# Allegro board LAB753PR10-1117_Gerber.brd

Outline 342 x 150.28 mm; copper layers: TOP, GND1, IN1, IN2, VCC, IN3, IN4, GND2, IN5, IN6, GND3, BOTTOM. Coordinates in mm from the lower left corner of the outline.

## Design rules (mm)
net group BUF_CLK1: nets BUF_CLK1 BUF_CLK+
net group DIFFPAIR0: nets EDP_TX0#_C EDP_TX0_C
net group DIFFPAIR1: nets EDP_TX1#_C EDP_TX1_C
net group DIFFPAIR2: nets EDP_TX2#_C EDP_TX2_C
net group DIFFPAIR3: nets EDP_TX3#_C EDP_TX3_C
net group DIFFPAIR4: nets EDP_AUX#_C EDP_AUX_C
net group DIFFPAIR8: nets CLK_BUF_BCLK CLK_BUF_BCLK#
net group DIFFPAIR9: nets CLK_BUF_CKSSCD CLK_BUF_CKSSCD#
net group DIFFPAIR11: nets CPU_EDP_AUX CPU_EDP_AUX#
net group DIFFPAIR12: nets CLK_PCIE_LAN CLK_PCIE_LAN#
net group DIFFPAIR13: nets CLK_BUF_DMI CLK_BUF_DMI#
net group DIFFPAIR14: nets CLK_BUF_DOT96 CLK_BUF_DOT96#
net group DIFFPAIR15: nets CLK_CPU_DMI CLK_CPU_DMI#
net group DIFFPAIR16: nets CLK_CPU_DPLL CLK_CPU_DPLL#
net group DIFFPAIR17: nets CLK_CPU_SSC_DPLL CLK_CPU_SSC_DPLL#
net group DIFFPAIR18: nets CLK_PCIE_CD CLK_PCIE_CD#
net group DIFFPAIR19: nets CLK_PCIE_DGPU CLK_PCIE_DGPU#
net group DIFFPAIR22: nets CPU_DPB_CTRLCLK_R CPU_DPB_CTRLDAT_R
net group DIFFPAIR26: nets EC_SMB_CK1 EC_SMB_DA1
net group DIFFPAIR27: nets EC_SMB_CK2 EC_SMB_DA2
net group DIFFPAIR45: nets I2C_CLK I2C_DAT
net group DIFFPAIR47: nets M_CLK_DDR0 M_CLK_DDR#0
net group DIFFPAIR48: nets M_CLK_DDR1 M_CLK_DDR#1
net group DIFFPAIR49: nets M_CLK_DDR2 M_CLK_DDR#2
net group DIFFPAIR50: nets M_CLK_DDR3 M_CLK_DDR#3
net group DIFFPAIR55: nets PEX_TSTCLK_OUT PEX_TSTCLK_OUT#
net group DIFFPAIR61: nets VGA_SMB_CK2 VGA_SMB_DA2
net group DIFFPAIR65: nets CLK_PCIE_DGPU#_C CLK_PCIE_DGPU_C
net group DIFFPAIR66: nets VCCSENSE_VGA VSSSENSE_VGA
net group DIFFPAIR70: nets CSSN_1 CSSP_1
net group DIFFPAIR74: nets USB3RN5_L USB3RP5_L
net group DIFFPAIR77: nets PEG_GTX_HRX_C_N8 PEG_GTX_HRX_C_P8
net group DIFFPAIR78: nets PEG_GTX_HRX_C_N9 PEG_GTX_HRX_C_P9
net group DIFFPAIR79: nets PEG_GTX_HRX_C_N10 PEG_GTX_HRX_C_P10
net group DIFFPAIR80: nets PEG_GTX_HRX_C_N11 PEG_GTX_HRX_C_P11
net group DIFFPAIR85: nets TP_CLK TP_DATA
net group DIFFPAIR86: nets SATA_PTX_DRX_N5_C SATA_PTX_DRX_P5_C
net group DIFFPAIR87: nets SATA_PRX_DTX_N5_C SATA_PRX_DTX_P5_C
net group DIFFPAIR88: nets I2C_CLK_347 I2C_DAT_347
net group DIFFPAIR89: nets CDR_I2C_CLK CDR_I2C_DAT
net group DP1: nets DDR_A_DQS0 DDR_A_DQS#0
net group DP2: nets DDR_A_DQS1 DDR_A_DQS#1
net group DP3: nets DDR_A_DQS2 DDR_A_DQS#2
net group DP4: nets DDR_A_DQS3 DDR_A_DQS#3
net group DP5: nets DDR_A_DQS4 DDR_A_DQS#4
net group DP6: nets DDR_A_DQS5 DDR_A_DQS#5
net group DP7: nets DDR_A_DQS6 DDR_A_DQS#6
net group DP8: nets DDR_A_DQS7 DDR_A_DQS#7
net group DP9: nets DDR_B_DQS0 DDR_B_DQS#0
net group DP10: nets DDR_B_DQS1 DDR_B_DQS#1
net group DP11: nets DDR_B_DQS2 DDR_B_DQS#2
net group DP12: nets DDR_B_DQS3 DDR_B_DQS#3
net group DP13: nets DDR_B_DQS4 DDR_B_DQS#4
net group DP14: nets DDR_B_DQS5 DDR_B_DQS#5
net group DP15: nets DDR_B_DQS6 DDR_B_DQS#6
net group DP16: nets DDR_B_DQS7 DDR_B_DQS#7
net group DP17: nets FBA_CLK0 FBA_CLK0#
net group DP18: nets FBA_CLK1 FBA_CLK1#
net group DP19: nets FBA_WCK0 FBA_WCK0_N
net group DP20: nets FBA_WCK1 FBA_WCK1_N
net group DP21: nets FBA_WCK2 FBA_WCK2_N
net group DP22: nets FBA_WCK3 FBA_WCK3_N
net group FBC_CLK0: nets FBC_CLK0 FBC_CLK0#
net group FBC_CLK1: nets FBC_CLK1 FBC_CLK1#
net group FBC_WCK0: nets FBC_WCK0 FBC_WCK0_N
net group FBC_WCK1: nets FBC_WCK1 FBC_WCK1_N
net group FBC_WCK2: nets FBC_WCK2 FBC_WCK2_N
net group FBC_WCK3: nets FBC_WCK3 FBC_WCK3_N
net group PCIE_PRX_LANTX_3_C: nets PCIE_PRX_LANTX_N3_C PCIE_PRX_LANTX_P3_C
net group PECI: nets H_PECI PECI_KB9012
net group SATA_PRX_DTX_P1_C: nets SATA_PRX_DTX_N1_C SATA_PRX_DTX_P1_C
net group SATA_PRX_DTX_P3_C: nets SATA_PRX_DTX_N3_C SATA_PRX_DTX_P3_C
net group SATA_PRX_DTX_P4_C: nets SATA_PRX_DTX_N4_C SATA_PRX_DTX_P4_C
net group SATA_PTX_DRX_P1_C: nets SATA_PTX_DRX_N1_C SATA_PTX_DRX_P1_C
net group SATA_PTX_DRX_P3_C: nets SATA_PTX_DRX_N3_C SATA_PTX_DRX_P3_C
net group SATA_PTX_DRX_P4_C: nets SATA_PTX_DRX_N4_C SATA_PTX_DRX_P4_C
net group SML0: nets SML0CLK SML0DATA
net group 8: nets CFG0 CFG1 CFG2 CFG3 CFG4 CFG5 CFG6 CFG7 CFG8 CFG9 CFG10 CFG11 CFG12 CFG13 CFG14 CFG15 CFG16 CFG17 CFG18 CFG19
net group 10: nets AMP_LEFT AMP_LEFT_C AMP_RIGHT AMP_RIGHT_C HPOUT-L HPOUT-R MIC1 MIC1_C_L REMOTE1+ REMOTE1- REMOTE2+ REMOTE2- SPK_L1-_CONN SPK_L2+_CONN SPK_R1-_CONN SPK_R2+_CONN SPKL+ SPKL- SPKR+ SPKR-
net group 12: nets HDA_SPKR PCH_AZ_CODEC_SDIN0 PCH_AZ_CODEC_SDIN0_R PCH_AZ_CODEC_SDOUT PCH_AZ_CODEC_SYNC PCH_AZ_SDOUT PCH_AZ_SYNC PCH_AZ_SYNC_Q
net group 12/13.5: nets CPU_PLTRST# DDR3_DRAMRST# DGPU_PEX_RST# DGPU_PEX_RST#_R H_CPUPWRGD H_DRAMRST# H_PM_SYNC H_PROCHOT# H_PROCHOT#_R H_THERMTRIP# IMVP_PWRGD PCH_PLTRST# PCH_PWROK PCH_PWROK_R PCH_THRMTRIP#_R_R PLT_RST# PLT_RST#_R PM_APWROK_R PM_DRAM_PWRGD PM_DRAM_PWRGD_R PM_SYS_PWRGD_BUF SCLK SDA SYS_PWROK SYS_PWROK_R VCC_PGOOD VR_HOT# VR_HOT#1 XDP_TCLK
net group 15: nets PCH_AZ_BITCLK PCH_AZ_CODEC_BITCLK PCH_GPIO66 PEG_COMP SATA_COMP USBRBIAS
net group 20: nets +SA_DIMM_VREFDQ +SB_DIMM_VREFDQ +SM_VREF B+ CLK_PCH_14M CLK_PCI0 CLK_PCI1 CLK_PCI2 CLK_PCI_LPBACK CLK_PCI_LPC DMI_IREF DMI_RCOMP RJ45_MDI0+ RJ45_MDI0- RJ45_MDI1+ RJ45_MDI1- RJ45_MDI2+ RJ45_MDI2- RJ45_MDI3+ RJ45_MDI3- VCCSENSE VCCSENSE_R VSSSENSE VSSSENSE_R
net group 25: nets EDP_COMP SM_RCOMP0 SM_RCOMP1 SM_RCOMP2
net group 50: nets LAN_MDIN0 LAN_MDIN1 LAN_MDIN2 LAN_MDIN3 LAN_MDIP0 LAN_MDIP1 LAN_MDIP2 LAN_MDIP3
net group ASYNCHRONOUS: nets DGPU_HOLD_RST#
net group DDRA-CMD: nets DDR_A_BS0 DDR_A_BS1 DDR_A_BS2 DDR_A_CAS# DDR_A_MA0 DDR_A_MA1 DDR_A_MA2 DDR_A_MA3 DDR_A_MA4 DDR_A_MA5 DDR_A_MA6 DDR_A_MA7 DDR_A_MA8 DDR_A_MA9 DDR_A_MA10 DDR_A_MA11 DDR_A_MA12 DDR_A_MA13 DDR_A_MA14 DDR_A_MA15 DDR_A_RAS# DDR_A_WE#
net group DDRA-CTL: nets DDR_CKE0_DIMMA DDR_CKE1_DIMMA DDR_CS0_DIMMA# DDR_CS1_DIMMA# M_ODT0 M_ODT1
net group DDRA-D0: nets DDR_A_D0 DDR_A_D1 DDR_A_D2 DDR_A_D3 DDR_A_D4 DDR_A_D5 DDR_A_D6 DDR_A_D7
net group DDRA-D1: nets DDR_A_D8 DDR_A_D9 DDR_A_D10 DDR_A_D11 DDR_A_D12 DDR_A_D13 DDR_A_D14 DDR_A_D15
net group DDRA-D2: nets DDR_A_D16 DDR_A_D17 DDR_A_D18 DDR_A_D19 DDR_A_D20 DDR_A_D21 DDR_A_D22 DDR_A_D23
net group DDRA-D3: nets DDR_A_D24 DDR_A_D25 DDR_A_D26 DDR_A_D27 DDR_A_D28 DDR_A_D29 DDR_A_D30 DDR_A_D31
net group DDRA-D4: nets DDR_A_D32 DDR_A_D33 DDR_A_D34 DDR_A_D35 DDR_A_D36 DDR_A_D37 DDR_A_D38 DDR_A_D39
net group DDRA-D5: nets DDR_A_D40 DDR_A_D41 DDR_A_D42 DDR_A_D43 DDR_A_D44 DDR_A_D45 DDR_A_D46 DDR_A_D47
net group DDRA-D6: nets DDR_A_D48 DDR_A_D49 DDR_A_D50 DDR_A_D51 DDR_A_D52 DDR_A_D53 DDR_A_D54 DDR_A_D55
net group DDRA-D7: nets DDR_A_D56 DDR_A_D57 DDR_A_D58 DDR_A_D59 DDR_A_D60 DDR_A_D61 DDR_A_D62 DDR_A_D63
net group DDRB-CMD: nets DDR_B_BS0 DDR_B_BS1 DDR_B_BS2 DDR_B_CAS# DDR_B_MA0 DDR_B_MA1 DDR_B_MA2 DDR_B_MA3 DDR_B_MA4 DDR_B_MA5 DDR_B_MA6 DDR_B_MA7 DDR_B_MA8 DDR_B_MA9 DDR_B_MA10 DDR_B_MA11 DDR_B_MA12 DDR_B_MA13 DDR_B_MA14 DDR_B_MA15 DDR_B_RAS# DDR_B_WE#
net group DDRB-CTL: nets DDR_CKE2_DIMMB DDR_CKE3_DIMMB DDR_CS2_DIMMB# DDR_CS3_DIMMB# M_ODT2 M_ODT3
net group DDRB-D0: nets DDR_B_D0 DDR_B_D1 DDR_B_D2 DDR_B_D3 DDR_B_D4 DDR_B_D5 DDR_B_D6 DDR_B_D7
net group DDRB-D1: nets DDR_B_D8 DDR_B_D9 DDR_B_D10 DDR_B_D11 DDR_B_D12 DDR_B_D13 DDR_B_D14 DDR_B_D15
net group DDRB-D2: nets DDR_B_D16 DDR_B_D17 DDR_B_D18 DDR_B_D19 DDR_B_D20 DDR_B_D21 DDR_B_D22 DDR_B_D23
net group DDRB-D3: nets DDR_B_D24 DDR_B_D25 DDR_B_D26 DDR_B_D27 DDR_B_D28 DDR_B_D29 DDR_B_D30 DDR_B_D31
net group DDRB-D4: nets DDR_B_D32 DDR_B_D33 DDR_B_D34 DDR_B_D35 DDR_B_D36 DDR_B_D37 DDR_B_D38 DDR_B_D39
net group DDRB-D5: nets DDR_B_D40 DDR_B_D41 DDR_B_D42 DDR_B_D43 DDR_B_D44 DDR_B_D45 DDR_B_D46 DDR_B_D47
net group DDRB-D6: nets DDR_B_D48 DDR_B_D49 DDR_B_D50 DDR_B_D51 DDR_B_D52 DDR_B_D53 DDR_B_D54 DDR_B_D55
net group DDRB-D7: nets DDR_B_D56 DDR_B_D57 DDR_B_D58 DDR_B_D59 DDR_B_D60 DDR_B_D61 DDR_B_D62 DDR_B_D63
net group DIFFPAIR46: nets MIC_DATA
net group DMI: nets DMI_CRX_PTX_N0 DMI_CRX_PTX_N1 DMI_CRX_PTX_N2 DMI_CRX_PTX_N3 DMI_CRX_PTX_P0 DMI_CRX_PTX_P1 DMI_CRX_PTX_P2 DMI_CRX_PTX_P3 DMI_CTX_PRX_N0 DMI_CTX_PRX_N1 DMI_CTX_PRX_N2 DMI_CTX_PRX_N3 DMI_CTX_PRX_P0 DMI_CTX_PRX_P1 DMI_CTX_PRX_P2 DMI_CTX_PRX_P3
net group DP: nets CPU_MDP_N0 CPU_MDP_N1 CPU_MDP_N2 CPU_MDP_N3 CPU_MDP_P0 CPU_MDP_P1 CPU_MDP_P2 CPU_MDP_P3 MDP_LANE_N0_C MDP_LANE_N1_C MDP_LANE_N2_C MDP_LANE_N3_C MDP_LANE_P0_C MDP_LANE_P1_C MDP_LANE_P2_C MDP_LANE_P3_C PCH_DP_AUXN_C PCH_DP_AUXP_C PCH_DPC_AUX PCH_DPC_AUX#
net group EDP: nets CPU_EDP_TX0N CPU_EDP_TX0P CPU_EDP_TX1N CPU_EDP_TX1P CPU_EDP_TX2N CPU_EDP_TX2P CPU_EDP_TX3N CPU_EDP_TX3P
net group EMC: nets CLK_PCI3 CLK_PCI4 DISP_CLK_AUXP_CONN DISP_DAT_AUXN_CONN EC_ESB_CLK EC_ESB_DAT FC_D3 MIC_CLK PCH_AZ_CODEC_RST# PCH_AZ_RST# RJ45_CT0 RJ45_CT1 RJ45_CT2 RJ45_CT3 ROM_SCLK ROM_SCLK_R SPI_MOCLK SPI_MOCLK_R XTAL25_IN XTAL25_OUT XTAL_OUT XTALIN XTALOUT XTALSSIN XTLI XTLO
net group FBA-CMD: nets FBA_ABI#_H FBA_ABI#_L FBA_CAS#_H FBA_CAS#_L FBA_CKE_H FBA_CKE_L FBA_CS#_H FBA_CS#_L FBA_MA0_MA10_H FBA_MA0_MA10_L FBA_MA1_MA9_H FBA_MA1_MA9_L FBA_MA2_BA0_H FBA_MA2_BA0_L FBA_MA3_BA3_H FBA_MA3_BA3_L FBA_MA4_BA2_H FBA_MA4_BA2_L FBA_MA5_BA1_H FBA_MA5_BA1_L FBA_MA6_MA11_H FBA_MA6_MA11_L FBA_MA7_MA8_H FBA_MA7_MA8_L FBA_MA12_RFU_H FBA_MA12_RFU_L FBA_RAS#_H FBA_RAS#_L FBA_RST#_H FBA_RST#_L FBA_WE#_H FBA_WE#_L
net group FBA-D0: nets FBA_D0 FBA_D1 FBA_D2 FBA_D3 FBA_D4 FBA_D5 FBA_D6 FBA_D7
net group FBA-D1: nets FBA_D8 FBA_D9 FBA_D10 FBA_D11 FBA_D12 FBA_D13 FBA_D14 FBA_D15
net group FBA-D2: nets FBA_D16 FBA_D17 FBA_D18 FBA_D19 FBA_D20 FBA_D21 FBA_D22 FBA_D23
net group FBA-D3: nets FBA_D24 FBA_D25 FBA_D26 FBA_D27 FBA_D28 FBA_D29 FBA_D30 FBA_D31
net group FBA-D4: nets FBA_D32 FBA_D33 FBA_D34 FBA_D35 FBA_D36 FBA_D37 FBA_D38 FBA_D39
net group FBA-D5: nets FBA_D40 FBA_D41 FBA_D42 FBA_D43 FBA_D44 FBA_D45 FBA_D46 FBA_D47
net group FBA-D6: nets FBA_D48 FBA_D49 FBA_D50 FBA_D51 FBA_D52 FBA_D53 FBA_D54 FBA_D55
net group FBA-D7: nets FBA_D56 FBA_D57 FBA_D58 FBA_D59 FBA_D60 FBA_D61 FBA_D62 FBA_D63
net group FBA-DBI: nets FBA_DBI0# FBA_DBI1# FBA_DBI2# FBA_DBI3# FBA_DBI4# FBA_DBI5# FBA_DBI6# FBA_DBI7#
net group FBA-EDC: nets FBA_EDC0 FBA_EDC1 FBA_EDC2 FBA_EDC3 FBA_EDC4 FBA_EDC5 FBA_EDC6 FBA_EDC7
net group FBB-CLK: nets FBB_CLK0 FBB_CLK0# FBB_CLK1 FBB_CLK1#
net group FBB-CMD: nets FBB_ABI#_H FBB_ABI#_L FBB_CAS#_H FBB_CAS#_L FBB_CKE_H FBB_CKE_L FBB_CS#_H FBB_CS#_L FBB_MA0_MA10_H FBB_MA0_MA10_L FBB_MA1_MA9_H FBB_MA1_MA9_L FBB_MA2_BA0_H FBB_MA2_BA0_L FBB_MA3_BA3_H FBB_MA3_BA3_L FBB_MA4_BA2_H FBB_MA4_BA2_L FBB_MA5_BA1_H FBB_MA5_BA1_L FBB_MA6_MA11_H FBB_MA6_MA11_L FBB_MA7_MA8_H FBB_MA7_MA8_L FBB_MA12_RFU_H FBB_MA12_RFU_L FBB_RAS#_H FBB_RAS#_L FBB_RST#_H FBB_RST#_L FBB_WE#_H FBB_WE#_L
net group FBB-D0: nets FBB_D0 FBB_D1 FBB_D2 FBB_D3 FBB_D4 FBB_D5 FBB_D6 FBB_D7
net group FBB-D1: nets FBB_D8 FBB_D9 FBB_D10 FBB_D11 FBB_D12 FBB_D13 FBB_D14 FBB_D15
net group FBB-D2: nets FBB_D16 FBB_D17 FBB_D18 FBB_D19 FBB_D20 FBB_D21 FBB_D22 FBB_D23
net group FBB-D3: nets FBB_D24 FBB_D25 FBB_D26 FBB_D27 FBB_D28 FBB_D29 FBB_D30 FBB_D31
net group FBB-D4: nets FBB_D32 FBB_D33 FBB_D34 FBB_D35 FBB_D36 FBB_D37 FBB_D38 FBB_D39
net group FBB-D5: nets FBB_D40 FBB_D41 FBB_D42 FBB_D43 FBB_D44 FBB_D45 FBB_D46 FBB_D47
net group FBB-D6: nets FBB_D48 FBB_D49 FBB_D50 FBB_D51 FBB_D52 FBB_D53 FBB_D54 FBB_D55
net group FBB-D7: nets FBB_D56 FBB_D57 FBB_D58 FBB_D59 FBB_D60 FBB_D61 FBB_D62 FBB_D63
net group FBB-DBI: nets FBB_DBI0# FBB_DBI1# FBB_DBI2# FBB_DBI3# FBB_DBI4# FBB_DBI5# FBB_DBI6# FBB_DBI7#
net group FBB-EDC: nets FBB_EDC0 FBB_EDC1 FBB_EDC2 FBB_EDC3 FBB_EDC4 FBB_EDC5 FBB_EDC6 FBB_EDC7
net group FBB-WCK: nets FBB_WCK0 FBB_WCK0_N FBB_WCK1 FBB_WCK1_N FBB_WCK2 FBB_WCK2_N FBB_WCK3 FBB_WCK3_N
net group FBC-CMD: nets FBC_ABI#_H FBC_ABI#_L FBC_CAS#_H FBC_CAS#_L FBC_CKE_H FBC_CKE_L FBC_CS#_H FBC_CS#_L FBC_MA0_MA10_H FBC_MA0_MA10_L FBC_MA1_MA9_H FBC_MA1_MA9_L FBC_MA2_BA0_H FBC_MA2_BA0_L FBC_MA3_BA3_H FBC_MA3_BA3_L FBC_MA4_BA2_H FBC_MA4_BA2_L FBC_MA5_BA1_H FBC_MA5_BA1_L FBC_MA6_MA11_H FBC_MA6_MA11_L FBC_MA7_MA8_H FBC_MA7_MA8_L FBC_MA12_RFU_H FBC_MA12_RFU_L FBC_RAS#_H FBC_RAS#_L FBC_RST#_H FBC_RST#_L FBC_WE#_H FBC_WE#_L
net group FBC-D0: nets FBC_D0 FBC_D1 FBC_D2 FBC_D3 FBC_D4 FBC_D5 FBC_D6 FBC_D7
net group FBC-D1: nets FBC_D8 FBC_D9 FBC_D10 FBC_D11 FBC_D12 FBC_D13 FBC_D14 FBC_D15
net group FBC-D2: nets FBC_D16 FBC_D17 FBC_D18 FBC_D19 FBC_D20 FBC_D21 FBC_D22 FBC_D23
net group FBC-D3: nets FBC_D24 FBC_D25 FBC_D26 FBC_D27 FBC_D28 FBC_D29 FBC_D30 FBC_D31
net group FBC-D4: nets FBC_D32 FBC_D33 FBC_D34 FBC_D35 FBC_D36 FBC_D37 FBC_D38 FBC_D39
net group FBC-D5: nets FBC_D40 FBC_D41 FBC_D42 FBC_D43 FBC_D44 FBC_D45 FBC_D46 FBC_D47
net group FBC-D6: nets FBC_D48 FBC_D49 FBC_D50 FBC_D51 FBC_D52 FBC_D53 FBC_D54 FBC_D55
net group FBC-D7: nets FBC_D56 FBC_D57 FBC_D58 FBC_D59 FBC_D60 FBC_D61 FBC_D62 FBC_D63
net group FBC-DBI: nets FBC_DBI0# FBC_DBI1# FBC_DBI2# FBC_DBI3# FBC_DBI4# FBC_DBI5# FBC_DBI6# FBC_DBI7#
net group FBC-EDC: nets FBC_EDC0 FBC_EDC1 FBC_EDC2 FBC_EDC3 FBC_EDC4 FBC_EDC5 FBC_EDC6 FBC_EDC7
net group FBD-CLK: nets FBD_CLK0 FBD_CLK0# FBD_CLK1 FBD_CLK1#
net group FBD-CMD: nets FBD_ABI#_H FBD_ABI#_L FBD_CAS#_H FBD_CAS#_L FBD_CKE_H FBD_CKE_L FBD_CS#_H FBD_CS#_L FBD_MA0_MA10_H FBD_MA0_MA10_L FBD_MA1_MA9_H FBD_MA1_MA9_L FBD_MA2_BA0_H FBD_MA2_BA0_L FBD_MA3_BA3_H FBD_MA3_BA3_L FBD_MA4_BA2_H FBD_MA4_BA2_L FBD_MA5_BA1_H FBD_MA5_BA1_L FBD_MA6_MA11_H FBD_MA6_MA11_L FBD_MA7_MA8_H FBD_MA7_MA8_L FBD_MA12_RFU_H FBD_MA12_RFU_L FBD_RAS#_H FBD_RAS#_L FBD_RST#_H FBD_RST#_L FBD_WE#_H FBD_WE#_L
net group FBD-D0: nets FBD_D0 FBD_D1 FBD_D2 FBD_D3 FBD_D4 FBD_D5 FBD_D6 FBD_D7
net group FBD-D1: nets FBD_D8 FBD_D9 FBD_D10 FBD_D11 FBD_D12 FBD_D13 FBD_D14 FBD_D15
net group FBD-D2: nets FBD_D16 FBD_D17 FBD_D18 FBD_D19 FBD_D20 FBD_D21 FBD_D22 FBD_D23
net group FBD-D3: nets FBD_D24 FBD_D25 FBD_D26 FBD_D27 FBD_D28 FBD_D29 FBD_D30 FBD_D31 FBD_DBI3# FBD_EDC3
net group FBD-D4: nets FBD_D32 FBD_D33 FBD_D34 FBD_D35 FBD_D36 FBD_D37 FBD_D38 FBD_D39
net group FBD-D5: nets FBD_D40 FBD_D41 FBD_D42 FBD_D43 FBD_D44 FBD_D45 FBD_D46 FBD_D47
net group FBD-D6: nets FBD_D48 FBD_D49 FBD_D50 FBD_D51 FBD_D52 FBD_D53 FBD_D54 FBD_D55
net group FBD-D7: nets FBD_D56 FBD_D57 FBD_D58 FBD_D59 FBD_D60 FBD_D61 FBD_D62 FBD_D63
net group FBD-DBI: nets FBD_DBI0# FBD_DBI1# FBD_DBI2# FBD_DBI4# FBD_DBI5# FBD_DBI6# FBD_DBI7#
net group FBD-EDC: nets FBD_EDC0 FBD_EDC1 FBD_EDC2 FBD_EDC4 FBD_EDC5 FBD_EDC6 FBD_EDC7
net group FBD-WCK: nets FBD_WCK0 FBD_WCK0_N FBD_WCK1 FBD_WCK1_N FBD_WCK2 FBD_WCK2_N FBD_WCK3 FBD_WCK3_N
net group FDI: nets FDI_CSYNC FDI_INT FDI_IREF FDI_RCOMP
net group HDMI: nets CPU_HDMI_N0 CPU_HDMI_N1 CPU_HDMI_N2 CPU_HDMI_N3 CPU_HDMI_P0 CPU_HDMI_P1 CPU_HDMI_P2 CPU_HDMI_P3 TMDS_L_TX0N TMDS_L_TX0P TMDS_L_TX1N TMDS_L_TX1P TMDS_L_TX2N TMDS_L_TX2P TMDS_L_TXCN TMDS_L_TXCP TMDS_TX0N TMDS_TX0N_C TMDS_TX0P TMDS_TX0P_C TMDS_TX1N TMDS_TX1N_C TMDS_TX1P TMDS_TX1P_C TMDS_TX2N TMDS_TX2N_C TMDS_TX2P TMDS_TX2P_C TMDS_TXCN TMDS_TXCN_C TMDS_TXCP TMDS_TXCP_C
net group PCIE: nets PCIE_PRX_C_DTX_N1 PCIE_PRX_C_DTX_P1 PCIE_PRX_CARDTX_N5 PCIE_PRX_CARDTX_P5 PCIE_PRX_GLANTX_N3 PCIE_PRX_GLANTX_P3 PCIE_PRX_WLANTX_N4 PCIE_PRX_WLANTX_P4 PCIE_PTX_CARDRX_N5 PCIE_PTX_CARDRX_N5_C PCIE_PTX_CARDRX_P5 PCIE_PTX_CARDRX_P5_C PCIE_PTX_GLANRX_N3 PCIE_PTX_GLANRX_N3_C PCIE_PTX_GLANRX_P3 PCIE_PTX_GLANRX_P3_C PCIE_PTX_WLANRX_N4 PCIE_PTX_WLANRX_N4_C PCIE_PTX_WLANRX_P4 PCIE_PTX_WLANRX_P4_C
net group PEG: nets CRX_N8 CRX_N9 CRX_N10 CRX_N11 CRX_P8 CRX_P9 CRX_P10 CRX_P11 PEG_GTX_HRX_N0 PEG_GTX_HRX_N0_C PEG_GTX_HRX_N1 PEG_GTX_HRX_N1_C PEG_GTX_HRX_N2 PEG_GTX_HRX_N2_C PEG_GTX_HRX_N3 PEG_GTX_HRX_N3_C PEG_GTX_HRX_N4 PEG_GTX_HRX_N4_C PEG_GTX_HRX_N5 PEG_GTX_HRX_N5_C PEG_GTX_HRX_N6 PEG_GTX_HRX_N6_C PEG_GTX_HRX_N7 PEG_GTX_HRX_N7_C PEG_GTX_HRX_N8 PEG_GTX_HRX_N9 PEG_GTX_HRX_N10 PEG_GTX_HRX_N11 PEG_GTX_HRX_P0 PEG_GTX_HRX_P0_C PEG_GTX_HRX_P1 PEG_GTX_HRX_P1_C PEG_GTX_HRX_P2 PEG_GTX_HRX_P2_C PEG_GTX_HRX_P3 PEG_GTX_HRX_P3_C PEG_GTX_HRX_P4 PEG_GTX_HRX_P4_C PEG_GTX_HRX_P5 PEG_GTX_HRX_P5_C PEG_GTX_HRX_P6 PEG_GTX_HRX_P6_C PEG_GTX_HRX_P7 PEG_GTX_HRX_P7_C PEG_GTX_HRX_P8 PEG_GTX_HRX_P9 PEG_GTX_HRX_P10 PEG_GTX_HRX_P11 PEG_HTX_C_GRX_N0 PEG_HTX_C_GRX_N1 PEG_HTX_C_GRX_N2 PEG_HTX_C_GRX_N3 PEG_HTX_C_GRX_N4 PEG_HTX_C_GRX_N5 PEG_HTX_C_GRX_N6 PEG_HTX_C_GRX_N7 PEG_HTX_C_GRX_N8 PEG_HTX_C_GRX_N9 PEG_HTX_C_GRX_N10 PEG_HTX_C_GRX_N11 PEG_HTX_C_GRX_P0 PEG_HTX_C_GRX_P1 PEG_HTX_C_GRX_P2 PEG_HTX_C_GRX_P3 PEG_HTX_C_GRX_P4 PEG_HTX_C_GRX_P5 PEG_HTX_C_GRX_P6 PEG_HTX_C_GRX_P7 PEG_HTX_C_GRX_P8 PEG_HTX_C_GRX_P9 PEG_HTX_C_GRX_P10 PEG_HTX_C_GRX_P11 PEG_HTX_GRX_N0 PEG_HTX_GRX_N1 PEG_HTX_GRX_N2 PEG_HTX_GRX_N3 PEG_HTX_GRX_N4 PEG_HTX_GRX_N5 PEG_HTX_GRX_N6 PEG_HTX_GRX_N7 PEG_HTX_GRX_N8 PEG_HTX_GRX_N9 PEG_HTX_GRX_N10 PEG_HTX_GRX_N11 PEG_HTX_GRX_P0 PEG_HTX_GRX_P1 PEG_HTX_GRX_P2 PEG_HTX_GRX_P3 PEG_HTX_GRX_P4 PEG_HTX_GRX_P5 PEG_HTX_GRX_P6 PEG_HTX_GRX_P7 PEG_HTX_GRX_P8 PEG_HTX_GRX_P9 PEG_HTX_GRX_P10 PEG_HTX_GRX_P11
net group PLATFORM-CLK: nets CLK_PCIE_WLAN CLK_PCIE_WLAN# CLK_PCIE_WLAN#_R CLK_PCIE_WLAN_R CLK_PEG_GPU CLK_PEG_GPU# PCH_DPB_HDMI_CLK PCH_DPB_HDMI_DAT PCH_DPC_CLK PCH_DPC_DAT
net group RTC: nets PCH_RTCRST# PCH_RTCX1 PCH_RTCX1_R PCH_RTCX2 SRTCRST#
net group SATA: nets SATA_PRX_DTX_N0 SATA_PRX_DTX_N0_C SATA_PRX_DTX_N0_R SATA_PRX_DTX_N0_RC SATA_PRX_DTX_N1 SATA_PRX_DTX_N3 SATA_PRX_DTX_N4 SATA_PRX_DTX_N5 SATA_PRX_DTX_P0 SATA_PRX_DTX_P0_C SATA_PRX_DTX_P0_R SATA_PRX_DTX_P0_RC SATA_PRX_DTX_P1 SATA_PRX_DTX_P3 SATA_PRX_DTX_P4 SATA_PRX_DTX_P5 SATA_PTX_DRX_N0 SATA_PTX_DRX_N0_C SATA_PTX_DRX_N0_R SATA_PTX_DRX_N0_RC SATA_PTX_DRX_N1 SATA_PTX_DRX_N3 SATA_PTX_DRX_N4 SATA_PTX_DRX_N5 SATA_PTX_DRX_P0 SATA_PTX_DRX_P0_C SATA_PTX_DRX_P0_R SATA_PTX_DRX_P0_RC SATA_PTX_DRX_P1 SATA_PTX_DRX_P3 SATA_PTX_DRX_P4 SATA_PTX_DRX_P5
net group SD: nets SD_CD# SD_CLK MS_D0 SD_CLK MS_D0_R SD_CMD MS_D2 SD_CMD MS_D2_R SD_D0 MS_D1 SD_D0 MS_D1_R SD_D1 SD_D1_R SD_D2 MS_CLK SD_D2 MS_CLK_R SD_D3 MS_D3 SD_D3 MS_D3_R SD_WP MS_BS
net group SMBUS: nets BUF_SM_CLK BUF_SM_DAT MEM_SMBCLK MEM_SMBDATA PCH_SMBCLK PCH_SMBDATA SML1CLK SML1DATA
net group SPI: nets PCH_SPI_CLK PCH_SPI_CLK_R PCH_SPI_CS0# PCH_SPI_DO2 PCH_SPI_DO3 PCH_SPI_S0_R PCH_SPI_SI PCH_SPI_SI_R PCH_SPI_SO SPI_PCH_DO2_R SPI_PCH_DO3_R
net group SVID: nets ALERT# H_CPU_SVIDALRT# VIDALERT_N VIDSCLK VIDSOUT
net group USB20: nets USB20_CAM_N6_R USB20_CAM_P6_R USB20_N0 USB20_N0_CONN USB20_N1 USB20_N1_CONN USB20_N2 USB20_N2_CONN USB20_N3 USB20_N4 USB20_N5 USB20_N6 USB20_N7 USB20_N7_CONN USB20_N8 USB20_N8_CONN USB20_P0 USB20_P0_CONN USB20_P1 USB20_P1_CONN USB20_P2 USB20_P2_CONN USB20_P3 USB20_P4 USB20_P5 USB20_P6 USB20_P7 USB20_P7_CONN USB20_P8 USB20_P8_CONN
net group USB30: nets USB3RN1 USB3RN1_R USB3RN2 USB3RN2_R USB3RN3 USB3RN3_R USB3RN5 USB3RN5_R USB3RN6 USB3RN6_R USB3RP1 USB3RP1_R USB3RP2 USB3RP2_R USB3RP3 USB3RP3_R USB3RP5 USB3RP5_R USB3RP6 USB3RP6_R USB3TN1 USB3TN1_L USB3TN1_R USB3TN2 USB3TN2_L USB3TN2_R USB3TN3 USB3TN3_L USB3TN3_R USB3TN5 USB3TN5_R USB3TN6 USB3TN6_L USB3TN6_R USB3TP1 USB3TP1_L USB3TP1_R USB3TP2 USB3TP2_L USB3TP2_R USB3TP3 USB3TP3_L USB3TP3_R USB3TP5 USB3TP5_R USB3TP6 USB3TP6_L USB3TP6_R
net group XDP: nets XDP_BPM#0_R XDP_BPM#1_R XDP_BPM#2 XDP_BPM#3 XDP_BPM#4 XDP_BPM#5 XDP_BPM#6 XDP_BPM#7 XDP_DBRESET# XDP_DBRESET#_R XDP_PRDY# XDP_PREQ# XDP_TDI_R XDP_TDO_R XDP_TMS XDP_TRST#
nets with their own width: min track width 0.254; nets 3V3_MAIN_EN +1.35VS_VGAP AC/DC AM0 AM1 AM2 DIR_SEL ECAGND FBVDD_EN GPU_PGOOD HP2_D_L1 HP2_D_L2 HP2_D_R1 HP2_D_R2 JACK1_PLUG JACK1_PLUG# JACK1_PLUG_C JACK2_PLUG# MEM_VREF MIC_BIAS_B MIC_BIAS_C MIC_C_PLUG MIC_LINE_IN_L MIC_LINE_IN_R MPIO_2 MPIO_4_PB#_PD SENSE A# SPK_MUTE SPK_MUTE# SPK_MUTE#_R VCIN0_PH VDDQ_PLL
nets with their own width: min track width 0.508; nets 2.5VOUT +1.05V_+1.5V_RUN +1.5VS +1.35V +1.35V_PWRGD +1.35VS_VGA +1.35VS_VGAP_B+ +3.3V_AVDD +3.3V_DVDD +3.3V_F347_1 +3.3V_GFX_AON +3V_PCH +3VALW +3VLP +3VS +3VS_CAM +3VS_TOUCH +3VS_VGA +5VALW +5VALW_LED +5VS +AV12_DV12_S +AVDDL +DV33_18 +FB_PLLAVDD +FBA_VREFC +FBA_VREFD +FBB_VREFD +PCH_VCCDSW +PCH_VCCDSW3_3 +PCH_VCCDSW_R +V_TP +VCCIO_OUT +VREF_DQ_DIMMA +VREF_DQ_DIMMB AGND AMP_RIGHT-1 CPU_EDP_HPD DVDD_HDAIO GND I2C_CTL_EN N19248975 N21560268 N30064642 SNUB_+1.05V_GPUP
nets with their own width: min track width 1.016; nets +1.2VS +1.05VS_VGA +3.3V_F347 +3VS_DP +5VS_TP_LED +LAN_IO +PAVDD +PCH_VCCCFUSE +PVDD +VCC_3IN1 +VDD_TOUCH GPU_PLLVDD N27543768
nets with their own width: min track width 1.524; nets +0.675VS +3VS_CARD +HDMI_5V_OUT +INV_PWR_SRC +LCDVDD_CONN B+_BIAS
nets with their own width: min track width 2.032; nets +3VS_WLAN_NGFF +USB3_VCCA +USB3_VCCB
nets with their own width: min track width 2.286; nets +1.35VS_VGAP_B++
nets with their own width: min track width 4.064; nets +1.05VS

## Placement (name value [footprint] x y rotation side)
C1  0.1U_0402_16V7K  [C_0402]  117 49.47 90 top
C2  0.1U_0402_16V7K  [C_0402]  117.87 49.47 90 top
C3  22U_0805_6.3V6M  [C_0805]  105.95 63.27 180 top
C4  22U_0805_6.3V6M  [C_0805]  119.51 52.12 270 top
C5  22U_0805_6.3V6M  [C_0805]  108.93 52.86 180 top
C6  22U_0805_6.3V6M  [C_0805]  108.93 56.42 180 top
C7  22U_0805_6.3V6M  [C_0805]  108.93 54.64 180 top
C8  22U_0805_6.3V6M  [C_0805]  121.29 52.12 270 top
C9  0.022U_0402_16V7K  [C_0402]  80.75 42.78 270 bottom
C10  1U_0402_6.3V6K  [C_0402]  143.12 17.17 0 top
C11  0.1U_0402_16V7K  [C_0402]  143.12 18.06 0 top
C12  0.1U_0402_16V7K  [C_0402]  141.86 24.59 90 top
C13  0.1U_0402_16V7K  [C_0402]  142.75 24.59 90 top
C14  0.1U_0402_16V7K  [C_0402]  100.85 15.65 180 top
C15  2.2U_0603_10V6K  [C_0603]  101.09 14.57 180 top
C16  0.1U_0402_16V7K  [C_0402]  140.5 26.88 0 top
C17  0.1U_0402_16V4Z  [C_0402]  166.83 146.42 90 top
C27  0.1U_0402_16V4Z  [C_0402]  180.84 16.12 180 top
C29  0.1U_0402_16V4Z  [C_0402]  214.82 125.17 90 bottom
C256  10U_0603_6.3V6M  [C_0603]  61.6 14.76 270 top
C257  10U_0603_6.3V6M  [C_0603]  60.39 14.76 270 top
C258  0.1U_0402_16V7K  [C_0402]  52.61 14.81 0 bottom
C260  10U_0603_6.3V6M  [C_0603]  60.39 12.16 0 top
C261  10U_0603_6.3V6M  [C_0603]  60.52 10.44 270 top
C262  10U_0603_6.3V6M  [C_0603]  53.53 9.74 0 top
C263  10U_0603_6.3V6M  [C_0603]  53.53 11.01 0 top
C264  10U_0603_6.3V6M  [C_0603]  53.6 17.3 0 top
C265  10U_0603_6.3V6M  [C_0603]  53.6 16.03 0 top
C266  10U_0603_6.3V6M  [C_0603]  222.2 16.84 270 top
C267  10U_0603_6.3V6M  [C_0603]  223.41 16.84 270 top
C268  0.01U_0603_25V7K  [C_0603]  215.78 13.29 180 top
C269  10U_0603_6.3V6M  [C_0603]  215.78 14.56 180 top
C270  10U_0603_6.3V6M  [C_0603]  215.78 15.83 180 top
C2498  0.1U_0402_10V6K  [C_0402]  148.66 15.78 90 bottom
C2500  2200P_0402_25V7K  [C_0402]  129.67 117.07 270 top
C2502  2200P_0402_25V7K  [C_0402]  149.77 15.29 270 bottom
C2504  2200P_0402_25V7K  [C_0402]  149.76 13.55 270 bottom
C2505  2200P_0402_25V7K  [C_0402]  200.54 49.87 135 bottom
C2506  220P_0402_50V8J  [C_0402]  57.67 13.87 0 top
C2507  470P_0402_50V7K  [C_0402]  57.67 12.98 0 top
C2508  1U_0603_10V4Z~D  [C_0603]  210 125.52 90 bottom
C2509  0.1U_0402_25V6K~D  [C_0402]  212.17 121.71 180 bottom
CA1  0.1U_0402_25V6K~D  [C_0402]  22.29 17.13 0 bottom
CA3  0.1U_0402_25V6K~D  [C_0402]  15.98 17.4 180 bottom
CA4  0.1U_0402_25V6K~D  [C_0402]  18.01 21 0 top
CA5  10U_0603_6.3V6M~D  [C_0603]  18 22.15 90 top
CA6  10U_0603_6.3V6M~D  [C_0603]  16.63 9.54 225 top
CA7  0.1U_0402_25V6K~D  [C_0402]  20.28 8.74 90 top
CA8  0.1U_0402_25V6K~D  [C_0402]  18.85 7.41 90 bottom
CA9  0.1U_0402_25V6K~D  [C_0402]  22.27 15.05 0 bottom
CA10  0.1U_0402_25V6K~D  [C_0402]  20.4 18.93 180 bottom
CA11  0.1U_0402_25V6K~D  [C_0402]  16 19.73 270 bottom
CA13  2.2U_0603_10V6K  [C_0603]  25.19 12.92 0 bottom
CA14  0.1U_0402_25V6K~D  [C_0402]  22.4 20.86 180 top
CA15  2200P_0402_25V7K~D  [C_0402]  21.67 12.92 270 bottom
CA16  0.1U_0402_25V6K~D  [C_0402]  25.19 10.21 90 bottom
CA17  47U_0805_6.3V6M~D  [C_0805]  20.25 8.52 270 bottom
CA18  0.1U_0402_25V6K~D  [C_0402]  21.6 8.74 90 top
CA19  0.1U_0402_25V6K~D  [C_0402]  26.71 11.57 270 top
CA24  100P_0402_50V8J~D  [C_0402]  22.93 8.71 90 top
CA29  1000P_0402_50V7K  [C_0402]  34.15 16.25 270 top
CA30  10P_0402_50V8J~D  [C_0402]  24.01 21.86 90 top
CA31  1000P_0402_50V7K  [C_0402]  34.18 12.61 270 top
CA32  1000P_0402_50V7K  [C_0402]  34.19 9.95 90 top
CA33  1000P_0402_50V7K  [C_0402]  34.17 13.59 90 top
CA65  0.1U_0402_16V7K  [C_0402]  25.26 19.64 0 top
CA66  0.01U_0402_16V7K  [C_0402]  14.1 10.73 90 top
CA67  1U_0402_6.3V6K~D  [C_0402]  226.63 16.11 270 bottom
CA68  1U_0402_6.3V6K~D  [C_0402]  223.06 15.14 0 bottom
CA69  0.1U_0603  [C_0603]  28.84 10.31 0 top
CA70  0.1U_0603  [C_0603]  10.28 27.65 0 bottom
CA71  0.1U_0603  [C_0603]  22.96 14 180 bottom
CA72  0.01U_0402_16V7K  [C_0402]  13.21 10.73 90 top
CA73  0.1U_0402_16V7K  [C_0402]  21.67 10.25 90 bottom
CA74  0.1U_0402_16V7K  [C_0402]  16.03 11.86 90 bottom
CA75  0.1U_0402_16V7K  [C_0402]  29.39 10.4 180 bottom
CA76  2.2U_0603_10V6K  [C_0603]  22.9 12.6 270 bottom
CA77  2.2U_0603_10V6K  [C_0603]  24.12 12.05 270 bottom
CA81  10U_0603_6.3V6M~D  [C_0603]  5.12 6.4 0 bottom
CA83  330P_0402_50V  [C_0402]  4.66 19.17 270 bottom
CA84  330P_0402_50V  [C_0402]  3.71 19.17 270 bottom
CA85  330P_0402_50V  [C_0402]  1.72 20.91 270 bottom
CA86  330P_0402_50V  [C_0402]  2.59 20.89 270 bottom
CA89  220U_B2_2.5VM_R35M~D  [C_B2]  8.63 9.44 90 bottom
CA90  220U_B2_2.5VM_R35M~D  [C_B2]  11.88 10.94 90 bottom
CA94  1U_0603_25V6K  [C_0603]  3.05 31.71 180 bottom
CA95  1U_0603_25V6K  [C_0603]  3.05 30.51 180 bottom
CA96  1U_0603_25V6K  [C_0603]  7.47 19.1 0 bottom
CA97  1U_0603_25V6K  [C_0603]  7.47 20.33 0 bottom
CA98  10U_0805_25V6K  [C_0805]  9.81 21.85 90 bottom
CA99  1U_0603_25V6K  [C_0603]  6.96 31.26 45 bottom
CA100  1U_0603_25V6K  [C_0603]  7.83 30.39 45 bottom
CA101  0.1U_0402_16V4Z  [C_0402]  9.25 29.97 225 bottom
CA102  0.1U_0402_16V4Z  [C_0402]  5.09 32.9 270 bottom
CA103  0.1U_0402_16V4Z  [C_0402]  13.58 9.11 0 top
CA104  0.1U_0402_16V4Z  [C_0402]  8.47 7.41 0 top
CA105  2.2U_0603_10V6K  [C_0603]  11.62 8.85 270 top
CA106  2.2U_0603_10V6K  [C_0603]  10.42 8.85 270 top
CA107  0.22U_0603_25V7K  [C_0603]  6.29 19.65 135 bottom
CA108  0.22U_0603_25V7K  [C_0603]  3.64 22.3 315 bottom
CA109  0.22U_0603_25V7K  [C_0603]  1.78 29.43 270 bottom
CA110  0.22U_0603_25V7K  [C_0603]  2.97 23.03 135 bottom
CA112  1U_0402_10V6K  [C_0402]  27.26 16.35 180 bottom
CA113  2.2U_0603_10V6K  [C_0603]  10.95 17.01 90 bottom
CC1  0.22U_0402_16V7K  [C_0402]  154.93 82.43 0 bottom
CC2  0.22U_0402_16V7K  [C_0402]  152.59 83.87 0 bottom
CC3  0.22U_0402_16V7K  [C_0402]  154.93 85.2 0 bottom
CC4  0.22U_0402_16V7K  [C_0402]  152.9 86.8 0 bottom
CC5  0.22U_0402_16V7K  [C_0402]  154.93 88.01 0 bottom
CC6  0.22U_0402_16V7K  [C_0402]  153.09 89.47 0 bottom
CC7  0.22U_0402_16V7K  [C_0402]  154.93 90.79 0 bottom
CC8  0.22U_0402_16V7K  [C_0402]  152.59 92.06 0 bottom
CC9  0.22U_0402_16V7K  [C_0402]  168.53 138.04 90 bottom
CC10  0.22U_0402_16V7K  [C_0402]  170.44 139.03 90 bottom
CC11  0.22U_0402_16V7K  [C_0402]  172.37 137.92 90 bottom
CC12  0.22U_0402_16V7K  [C_0402]  174.39 139.22 90 bottom
CC13  0.22U_0402_16V7K  [C_0402]  154.93 81.5 0 bottom
CC14  0.22U_0402_16V7K  [C_0402]  152.59 82.94 0 bottom
CC15  0.22U_0402_16V7K  [C_0402]  154.93 84.27 0 bottom
CC16  0.22U_0402_16V7K  [C_0402]  152.9 85.87 0 bottom
CC17  0.22U_0402_16V7K  [C_0402]  154.93 87.08 0 bottom
CC18  0.22U_0402_16V7K  [C_0402]  153.09 88.49 0 bottom
CC19  0.22U_0402_16V7K  [C_0402]  154.93 89.86 0 bottom
CC20  0.22U_0402_16V7K  [C_0402]  152.59 91.13 0 bottom
CC21  0.22U_0402_16V7K  [C_0402]  167.62 138.04 90 bottom
CC22  0.22U_0402_16V7K  [C_0402]  169.55 139.03 90 bottom
CC23  0.22U_0402_16V7K  [C_0402]  171.48 137.92 90 bottom
CC24  0.22U_0402_16V7K  [C_0402]  173.47 139.22 90 bottom
CC27  100P_0402_50V8J  [C_0402]  93.54 64.87 270 top
CC28  0.1U_0402_16V7K  [C_0402]  91.76 63.1 270 top
CC29  100P_0402_50V8J  [C_0402]  91.24 96.8 0 top
CC30  0.1U_0402_16V7K  [C_0402]  88.64 64.8 0 top
CC31  0.01U_0402_16V7K  [C_0402]  82.67 63.02 0 top
CC32  2.2U_0603_10V6K  [C_0603]  88.97 103.92 180 bottom
CC33  10U_0603_6.3V6M  [C_0603]  107.25 79.78 180 top
CC34  10U_0603_6.3V6M  [C_0603]  109.67 79.78 180 top
CC35  10U_0603_6.3V6M  [C_0603]  119.64 79.78 0 top
CC36  10U_0603_6.3V6M  [C_0603]  117.22 79.78 0 top
CC37  10U_0603_6.3V6M  [C_0603]  115.95 79.78 180 top
CC38  10U_0603_6.3V6M  [C_0603]  112.14 79.78 0 top
CC39  10U_0603_6.3V6M  [C_0603]  121.73 63.46 0 top
CC40  10U_0603_6.3V6M  [C_0603]  105.79 64.73 180 top
CC41  10U_0603_6.3V6M  [C_0603]  121.73 64.73 0 top
CC42  10U_0603_6.3V6M  [C_0603]  104.84 79.78 180 top
CC43  330U_D2_2V_Y  [C_D2]  121.52 55.15 0 top
CC44  330U_D2_2V_Y  [C_D2]  111.98 59.78 180 top
CC45  0.1U_0402_10V7K  [C_0402]  126.81 108.34 90 top
CC46  22U_0805_6.3V6M  [C_0805]  125.41 108.46 90 top
CC47  22U_0805_6.3V6M  [C_0805]  124.78 52.12 270 top
CC48  22U_0805_6.3V6M  [C_0805]  121.58 61.94 0 top
CC49  22U_0805_6.3V6M  [C_0805]  121.58 60.16 0 top
CC50  22U_0805_6.3V6M  [C_0805]  121.58 58.38 0 top
CC51  22U_0805_6.3V6M  [C_0805]  123.07 52.12 270 top
CD1  2.2U_0603_10V6K  [C_0603]  83.61 44.54 270 bottom
CD2  0.1U_0402_16V7K  [C_0402]  82.53 44.62 270 bottom
CD3  1U_0402_6.3V6K  [C_0402]  142.99 38.32 0 top
CD4  0.1U_0402_16V7K  [C_0402]  143 39.21 0 top
CD5  0.1U_0402_16V7K  [C_0402]  143.12 30.13 0 top
CD6  0.1U_0402_16V7K  [C_0402]  143.12 31.02 0 top
CD7  10U_0603_6.3V6M  [C_0603]  114.05 43.27 90 bottom
CD8  10U_0603_6.3V6M  [C_0603]  115.7 43.27 90 bottom
CD9  10U_0603_6.3V6M  [C_0603]  102.94 43.27 90 bottom
CD10  10U_0603_6.3V6M  [C_0603]  105.22 43.27 90 bottom
CD11  10U_0603_6.3V6M  [C_0603]  108.65 43.27 90 bottom
CD12  10U_0603_6.3V6M  [C_0603]  111.25 43.27 90 bottom
CD13  10U_0603_6.3V6M  [C_0603]  118.94 43.27 90 bottom
CD14  10U_0603_6.3V6M  [C_0603]  117.29 43.27 90 bottom
CD15  0.1U_0402_16V7K  [C_0402]  110.17 43.51 90 bottom
CD16  0.1U_0402_16V7K  [C_0402]  104.08 43.51 90 bottom
CD17  0.1U_0402_16V7K  [C_0402]  107.51 43.51 90 bottom
CD18  0.1U_0402_16V7K  [C_0402]  112.97 43.51 90 bottom
CD19  0.1U_0402_16V7K  [C_0402]  123 45.35 90 bottom
CD20  2.2U_0603_10V6K  [C_0603]  124.97 45.43 90 bottom
CD21  0.022U_0402_16V7K  [C_0402]  126.05 47.77 90 bottom
CD22  2.2U_0603_10V6K  [C_0603]  137.86 43.65 90 bottom
CD23  0.1U_0402_16V7K  [C_0402]  138.94 43.64 90 bottom
CD24  2.2U_0603_10V6K  [C_0603]  74.87 16.16 0 top
CD25  0.1U_0402_16V7K  [C_0402]  74.78 24.4 180 top
CD26  10U_0603_6.3V6M  [C_0603]  108.42 15.22 270 top
CD27  10U_0603_6.3V6M  [C_0603]  110.71 15.22 270 top
CD28  10U_0603_6.3V6M  [C_0603]  111.98 15.22 270 top
CD29  10U_0603_6.3V6M  [C_0603]  115.22 15.22 270 top
CD30  10U_0603_6.3V6M  [C_0603]  107.15 15.22 270 top
CD31  10U_0603_6.3V6M  [C_0603]  105.87 15.22 270 top
CD32  10U_0603_6.3V6M  [C_0603]  117.76 15.22 270 top
CD33  10U_0603_6.3V6M  [C_0603]  116.49 15.22 270 top
CD34  0.1U_0402_16V7K  [C_0402]  109.5 14.98 270 top
CD35  0.1U_0402_16V7K  [C_0402]  113.12 14.98 270 top
CD36  0.1U_0402_16V7K  [C_0402]  104.71 15.28 270 top
CD37  0.1U_0402_16V7K  [C_0402]  103.82 15.28 270 top
CD38  0.022U_0402_16V7K  [C_0402]  73.87 21.55 0 top
CD39  2.2U_0603_10V6K  [C_0603]  140.91 43.78 90 top
CD40  330U_2.5V_M  [C_MP2VLPS330MC4R2]  116.61 11.67 180 bottom
CD41  10P_0402_50V8J  [C_0402]  143.12 18.95 0 top
CD42  10P_0402_50V8J  [C_0402]  119.31 37.11 270 top
CD43  10P_0402_50V8J  [C_0402]  142.99 37.43 0 top
CD44  10P_0402_50V8J  [C_0402]  114.07 14.98 270 top
CE1  1U_0805_10V7  [C_0805]  261.28 36.35 0 bottom
CE2  0.1U_0402_16V4Z~D  [C_0402]  262.6 34.11 45 bottom
CE3  0.1U_0402_16V4Z~D  [C_0402]  263.23 33.48 45 bottom
CE4  22P_0402_50V8J~D  [C_0402]  262 32.03 45 bottom
CE6  1U_0805_10V7  [C_0805]  265.81 35.94 135 bottom
CE7  0.1U_0402_16V4Z~D  [C_0402]  266.86 34.89 315 bottom
CE8  0.1U_0402_16V4Z~D  [C_0402]  273.05 23.91 315 bottom
CE9  0.1U_0402_16V4Z~D  [C_0402]  273.68 24.54 315 bottom
CE10  0.1U_0402_16V4Z  [C_0402]  262.01 33.31 225 bottom
CE13  0.1U_0402_16V4Z~D  [C_0402]  274.69 28.09 0 bottom
CE14  0.1U_0402_16V4Z~D  [C_0402]  274.69 28.98 0 bottom
CE15  0.1U_0402_16V4Z~D  [C_0402]  274.69 27.21 0 bottom
CE16  0.1U_0402_16V4Z~D  [C_0402]  270.46 31.74 45 bottom
CE17  0.1U_0402_16V4Z~D  [C_0402]  269.83 32.37 45 bottom
CE18  0.1U_0402_16V4Z~D  [C_0402]  269.23 33.02 45 bottom
CE19  0.1U_0402_16V4Z~D  [C_0402]  258.08 41.94 180 bottom
CE20  22P_0402_50V8J~D  [C_0402]  255.39 41.94 0 bottom
CE22  4.7U_0603_10V  [C_0603]  252.9 37.68 0 top
CE23  0.1U_0402_16V4Z  [C_0402]  225 121.13 270 top
CE24  0.1U_0402_16V4Z  [C_0402]  222.3 115.19 0 top
CE25  0.1U_0402_16V4Z  [C_0402]  154 18.19 270 top
CE26  0.1U_0402_16V4Z  [C_0402]  222.35 126.15 90 bottom
CE27  0.1U_0402_16V7K  [C_0402]  157.85 139.4 180 top
CE28  0.1U_0402_10V7K  [C_0402]  275.4 9.76 270 top
CE29  0.1U_0402_10V7K  [C_0402]  288.36 9.63 270 top
CE30  0.1U_0402_10V7K  [C_0402]  292.22 26.38 0 top
CE31  1000P_0402_50V7K  [C_0402]  286.58 30.77 270 top
CE32  1000P_0402_50V7K  [C_0402]  279.4 30.39 270 top
CE33  0.1U_0402_10V7K  [C_0402]  276.66 9.87 0 top
CE34  0.047U_0402_16V4Z  [C_0402]  283.85 29.48 90 top
CE35  100P_0402_50V8J  [C_0402]  272.8 12.97 90 top
CE36  0.1U_0402_10V7K  [C_0402]  285.69 30.77 270 top
CE37  0.1U_0402_10V7K  [C_0402]  271.71 24.22 180 top
CE38  0.1U_0402_10V7K  [C_0402]  295.14 24.6 0 top
CE40  100P_0402_50V8J  [C_0402]  294.98 20.22 270 top
CE41  0.1U_0402_10V7K  [C_0402]  287.53 29.86 90 top
CE42  0.1U_0402_10V7K  [C_0402]  287.28 9.63 270 top
CE43  0.1U_0402_10V7K  [C_0402]  290.13 8.71 90 top
CE44  0.1U_0402_10V7K  [C_0402]  276.1 29.54 90 top
CE45  0.1U_0402_10V7K  [C_0402]  282.96 29.48 90 top
CE46  0.1U_0402_10V7K  [C_0402]  284.42 9.63 270 top
CE48  4.7U_0805_10V4Z  [C_0805]  292.37 25.06 0 top
CE50  0.1U_0402_10V7K  [C_0402]  292.71 18.26 0 top
CE51  47P_0402_50V8J  [C_0402]  295.89 19.31 90 top
CE52  0.033U_0402_25V  [C_0402]  295.99 13.97 270 top
CE53  0.1U_0402_16V4Z  [C_0402]  183.5 137.99 0 bottom
CE55  .1U_0402_16V7K~D  [C_0402]  241.43 40.46 90 top
CE56  0.1U_0402_16V4Z  [C_0402]  236.45 44.25 180 top
CE57  10P_0402_50V8J  [C_0402]  252.81 41.94 180 bottom
CE58  10P_0402_50V8J  [C_0402]  260.62 22.61 135 top
CE59  10P_0402_50V8J  [C_0402]  261.37 33.94 225 bottom
CE60  10P_0402_50V8J  [C_0402]  267.46 35.53 315 bottom
CF2  100P_0402_50V8J  [C_0402]  217.57 120 180 bottom
CF3  470P_0402_50V7K  [C_0402]  201.84 127.57 180 bottom
CF4  22U_0805_6.3VAM  [C_0805]  65.7 57.86 180 bottom
CF5  22U_0805_6.3VAM  [C_0805]  240.65 52.61 0 bottom
CF6  0.1U_0402_10V7K  [C_0402]  203.8 129.47 270 bottom
CH1  15P_0402_50V8J~D  [C_0402]  230.35 22.79 0 top
CH2  15P_0402_50V8J~D  [C_0402]  233.06 24.53 180 top
CH3  1U_0402_6.3V6K~D  [C_0402]  237.38 29.76 180 bottom
CH4  1U_0402_6.3V6K~D  [C_0402]  237.38 28.5 180 bottom
CH5  27P_0402_50V8J~D  [C_0402]  236.02 42.01 0 bottom
CH6  0.1U_0402_25V6K~D  [C_0402]  211.39 21.1 90 top
CH7  0.1U_0402_25V6K~D  [C_0402]  222.63 21.03 90 top
CH8  12P_0402_50V8J  [C_0402]  216.4 51.34 180 bottom
CH9  12P_0402_50V8J  [C_0402]  217.6 51.34 0 bottom
CH10  0.1U_0402_25V6K~D  [C_0402]  217.05 14.87 90 bottom
CH11  22P_0402_50V8J~D  [C_0402]  210.75 23.51 90 top
CH12  0.1U_0402_25V6K  [C_0402]  207.57 42.57 0 bottom
CH13  0.1U_0402_25V6K  [C_0402]  207.57 43.46 0 bottom
CH14  0.1U_0402_25V6K  [C_0402]  207.57 45.29 0 bottom
CH15  0.1U_0402_25V6K  [C_0402]  207.57 44.35 0 bottom
CH16  0.1U_0402_25V6K  [C_0402]  207.57 46.17 0 bottom
CH17  0.1U_0402_25V6K  [C_0402]  207.57 47.11 0 bottom
CH18  10U_0603_6.3V6M~D  [C_0603]  240.16 35.14 90 top
CH19  1U_0402_6.3V6K~D  [C_0402]  220.39 37.36 180 top
CH20  1U_0402_6.3V6K~D  [C_0402]  221.24 38.16 270 top
CH21  1U_0402_6.3V6K~D  [C_0402]  219.81 35.99 0 top
CH22  1U_0402_6.3V6K~D  [C_0402]  216.75 45.54 180 top
CH23  10U_0603_6.3V6M~D  [C_0603]  212.51 47.46 90 top
CH24  0.1U_0402_10V7K~D  [C_0402]  224.25 42.13 0 top
CH25  0.1U_0402_10V7K~D  [C_0402]  220.4 40.54 0 top
CH26  22U_0805_6.3V6M~D  [C_0805]  223.94 50.83 0 bottom
CH27  1U_0402_6.3V6K~D  [C_0402]  222.48 35.97 180 top
CH28  1U_0402_6.3V6K~D  [C_0402]  223.34 35.97 0 top
CH29  10U_0603_6.3V6M~D  [C_0603]  212.32 45.26 180 top
CH30  10U_0603_6.3V6M~D  [C_0603]  211.38 37.56 0 top
CH31  10U_0603_6.3V6M~D  [C_0603]  213.92 34.57 180 top
CH32  1U_0402_6.3V6K~D  [C_0402]  219.89 38.99 180 top
CH33  1U_0402_6.3V6K~D  [C_0402]  217.26 38.3 90 top
CH34  1U_0402_6.3V6K~D  [C_0402]  216.37 38.22 180 top
CH35  1U_0402_6.3V6K~D  [C_0402]  217.75 37.36 0 top
CH36  10U_0603_6.3V6M~D  [C_0603]  241.43 35.14 90 top
CH37  1U_0402_6.3V6K~D  [C_0402]  229.5 22.77 270 top
CH38  0.1U_0402_10V7K~D  [C_0402]  230.01 34.99 90 top
CH39  0.1U_0402_10V7K~D  [C_0402]  223.25 40.6 180 top
CH40  0.1U_0402_10V7K~D  [C_0402]  223.89 48.86 0 top
CH41  0.1U_0402_10V7K~D  [C_0402]  223.19 37.36 180 top
CH42  0.1U_0402_10V7K~D  [C_0402]  221.08 34.35 0 top
CH43  0.1U_0402_10V7K~D  [C_0402]  226.11 38.25 180 top
CH44  0.1U_0402_10V7K~D  [C_0402]  219.97 34.21 90 top
CH45  1U_0402_6.3V6K~D  [C_0402]  223.31 42.13 180 top
CH46  0.1U_0402_10V7K~D  [C_0402]  230.39 39.14 135 top
CH47  10U_0603_6.3V6M~D  [C_0603]  214.37 47.14 0 top
CH48  1U_0402_6.3V6K~D  [C_0402]  227.34 33.94 180 top
CH49  0.1U_0402_10V7K~D  [C_0402]  224.44 34.37 180 top
CH50  0.1U_0402_10V7K~D  [C_0402]  230.24 30.22 90 top
CH51  0.1U_0402_10V7K~D  [C_0402]  231.57 29.16 0 top
CH52  1U_0402_6.3V6K~D  [C_0402]  231.87 28.17 0 top
CH53  1U_0402_6.3V6K~D  [C_0402]  222.65 47.06 180 top
CH54  1U_0402_6.3V6K~D  [C_0402]  220.18 29.48 180 top
CH55  0.1U_0402_10V7K~D  [C_0402]  219.11 34.2 90 top
CH56  0.1U_0402_10V7K~D  [C_0402]  218.27 34.39 180 top
CH57  1U_0402_6.3V6K~D  [C_0402]  218.06 35.99 0 top
CH58  0.1U_0402_10V7K~D  [C_0402]  218.56 40.72 180 top
CH59  10U_0603_6.3V6M~D  [C_0603]  219.03 47.72 180 top
CH60  1U_0402_6.3V6K~D  [C_0402]  219.99 46.87 0 top
CH61  1U_0402_6.3V6K~D  [C_0402]  220.6 42.39 270 top
CH62  1U_0402_6.3V6K~D  [C_0402]  219.99 47.76 0 top
CH63  1U_0402_6.3V6K~D  [C_0402]  220.32 43.63 0 top
CH64  1U_0402_6.3V6K~D  [C_0402]  219.48 42.19 180 top
CH65  1U_0402_6.3V6K~D  [C_0402]  224.97 37.36 180 top
CH66  1U_0402_6.3V6K~D  [C_0402]  228.34 39.91 315 top
CH67  1U_0402_6.3V6K~D  [C_0402]  228.91 40.79 0 top
CH68  1U_0402_6.3V6K~D  [C_0402]  225.12 39.21 180 top
CH69  1U_0402_6.3V6K~D  [C_0402]  224.12 40.6 0 top
CH70  10U_0603_6.3V6M~D  [C_0603]  211.81 55.91 0 top
CH71  1U_0402_6.3V6K~D  [C_0402]  216.7 47.88 270 top
CH72  10P_0402_50V8J  [C_0402]  229.57 49.52 180 top
CH100  10P_0402_50V8J~D  [C_0402]  336.63 34.27 90 top
CH101  0.1U_0402_16V4Z~D  [C_0402]  336.63 36.97 270 top
CI1  4.7U_0805_10V4Z  [C_0805]  316.74 56.9 90 bottom
CI2  0.1U_0402_16V7K  [C_0402]  318 58.66 0 bottom
CI4  0.1U_0402_16V7K  [C_0402]  318.06 54.32 0 bottom
CI5  0.1U_0402_16V7K  [C_0402]  320.75 54.32 180 bottom
CI10  47U_0805_6.3V6M~D  [C_0805]  322.07 57.65 270 bottom
CI11  10U_0603_6.3V6M~D  [C_0603]  323.6 57.49 270 bottom
CI24  47U_0805_6.3V6M~D  [C_0805]  321.31 43.55 270 bottom
CI25  10U_0603_6.3V6M~D  [C_0603]  323.28 43.33 270 bottom
CI26  4.7U_0805_10V4Z  [C_0805]  315.03 43.99 270 bottom
CI27  0.1U_0402_16V7K  [C_0402]  316.42 43.6 270 bottom
CI28  0.1U_0402_16V7K  [C_0402]  317.3 41.37 0 bottom
CI29  0.1U_0402_16V7K  [C_0402]  319.99 41.37 180 bottom
CI30  0.1U_0402_10V6K~D  [C_0402]  317.38 61.93 90 bottom
CI31  0.1U_0402_10V6K~D  [C_0402]  318.26 61.93 90 bottom
CI32  0.1U_0402_10V6K~D  [C_0402]  317.18 48.66 90 bottom
CI33  0.1U_0402_10V6K~D  [C_0402]  318.07 48.66 90 bottom
CI34  0.1U_0402_10V6K~D  [C_0402]  18.08 24.47 180 top
CI35  0.1U_0402_10V6K~D  [C_0402]  18.08 25.36 180 top
CI36  0.1U_0402_10V6K~D  [C_0402]  18.08 30.76 180 top
CI37  0.1U_0402_10V6K~D  [C_0402]  18.08 31.65 180 top
CI38  0.1U_0402_10V6K  [C_0402]  189.63 133.76 180 bottom
CI39  0.1U_0402_10V6K  [C_0402]  189.63 134.65 180 bottom
CI40  10P_0402_50V8J  [C_0402]  324.5 59.02 180 bottom
CI41  10P_0402_50V8J  [C_0402]  323.86 44.73 180 bottom
CL1  0.1U_0402_16V7K~D  [C_0402]  316.36 38.76 90 top
CL2  0.1U_0402_16V7K~D  [C_0402]  317.38 38.76 90 top
CL3  1U_0402_6.3V6K~D  [C_0402]  313.72 31.84 180 top
CL4  0.1U_0402_16V7K~D  [C_0402]  313.72 32.73 180 top
CL5  1U_0402_6.3V6K~D  [C_0402]  323.14 30.44 0 top
CL6  0.1U_0402_16V7K~D  [C_0402]  323.14 29.55 0 top
CL7  0.1U_0402_16V7K~D  [C_0402]  319.85 38.62 90 top
CL8  15P_0402_50V8J~D  [C_0402]  321.71 28.98 180 top
CL9  15P_0402_50V8J~D  [C_0402]  318.95 28.98 0 top
CL11  1000P_0402_50V7K~D  [C_0402]  314.73 29.06 270 top
CL12  0.1U_0402_16V7K~D  [C_0402]  313.84 29.06 270 top
CL13  1U_0402_6.3V6K~D  [C_0402]  312.96 29.06 270 top
CL14  10U_0603_6.3V6M~D  [C_0603]  312.02 28.35 180 top
CL15  10U_0603_6.3V6M~D  [C_0603]  312.02 29.55 180 top
CL16  0.1U_0402_16V7K~D  [C_0402]  323.14 33.75 0 top
CL17  1U_0402_6.3V6K~D  [C_0402]  323.14 34.63 0 top
CL18  1U_0402_6.3V6K~D  [C_0402]  317.96 28.08 180 top
CL19  0.1U_0402_16V7K~D  [C_0402]  317.96 28.98 180 top
CL20  0.1U_0402_16V7K~D  [C_0402]  313.7 34.52 270 top
CL21  1U_0402_6.3V6K~D  [C_0402]  312.82 34.52 270 top
CL22  4.7U_0603_6.3V6K~D  [C_0603]  311.74 34.51 270 top
CL23  0.1U_0402_16V7K~D  [C_0402]  313.3 35.93 90 top
CL24  0.1U_0402_16V7K~D  [C_0402]  323.14 32.79 0 top
CL25  0.1U_0402_16V7K~D  [C_0402]  323.14 35.97 0 top
CL27  470P_0402_50V7K  [C_0402]  321.5 89.13 270 top
CL28  470P_0402_50V7K  [C_0402]  324.68 76.43 270 top
CL29  470P_0402_50V7K  [C_0402]  323.85 74.46 270 top
CL30  10P_1808_3KV7K~D  [C_1808]  321.69 70.88 90 bottom
CL31  470P_0402_50V7K  [C_0402]  324.8 74.46 270 top
CL32  1000P_0402_50V7K~D  [C_0402]  326.01 79.01 90 top
CL33  0.1U_0402_16V7K~D  [C_0402]  329.88 79.92 270 top
CL34  1000P_0402_50V7K~D  [C_0402]  335.92 79.01 90 top
CL35  0.1U_0402_16V7K~D  [C_0402]  329 79.92 270 top
CL36  1000P_0402_50V7K~D  [C_0402]  331.98 79.01 90 top
CL37  0.1U_0402_16V7K~D  [C_0402]  326.9 79.92 270 top
CL38  1000P_0402_50V7K~D  [C_0402]  335.03 79.01 90 top
CL39  0.1U_0402_16V7K~D  [C_0402]  332.87 79.92 270 top
CL40  4.7U_0805_10V4Z  [C_0805]  331.26 35.02 0 top
CL41  0.1U_0402_16V7K  [C_0402]  331.65 33.68 0 top
CL42  0.1U_0402_16V7K  [C_0402]  330.96 32.74 270 top
CM9  0.1U_0402_10V7K  [C_0402]  154.23 127.9 270 bottom
CM10  100U_1206_6.3V6M  [C_1206]  164.28 15.52 180 bottom
CM11  1U_0402_6.3V6K  [C_0402]  155.49 16.33 0 bottom
CM12  22U_0603_6.3V6M~D  [C_0603]  169.29 24.22 0 top
CM13  0.1U_0402_10V7K~D  [C_0402]  173.14 17.91 0 top
CM14  22U_0603_6.3V6M~D  [C_0603]  173.17 16.64 0 top
CM15  0.1U_0402_10V7K~D  [C_0402]  169.53 23.14 0 top
CM16  0.1U_0402_10V7K  [C_0402]  225.2 123.26 180 bottom
CM17  0.1U_0402_10V7K  [C_0402]  225.2 124.14 180 bottom
CM18  0.1U_0402_10V7K  [C_0402]  219.14 112.55 270 bottom
CM19  22U_0603_6.3V6M  [C_0603]  224.68 126.35 180 bottom
CM20  0.1U_0402_10V7K  [C_0402]  222.3 116.08 0 top
CM21  1U_0402_6.3V  [C_0402]  222.51 123.23 90 bottom
CM23  0.1U_0402_10V7K  [C_0402]  192.6 139.22 90 bottom
CM24  10P_0402_50V8J  [C_0402]  155.49 17.29 0 bottom
CM25  10P_0402_50V8J  [C_0402]  164.2 17.32 180 bottom
CM26  10P_0402_50V8J  [C_0402]  170.52 35.54 180 top
CM27  10P_0402_50V8J  [C_0402]  161.39 17.32 0 bottom
CM28  10P_0402_50V8J  [C_0402]  155.7 21.95 270 top
CM29  10U_0805_10V4Z  [C_0805]  148.68 132.68 180 bottom
CM30  1U_0603_10V4Z  [C_0603]  149.54 131.28 270 bottom
CM31  10U_0805_10V4Z  [C_0805]  148.68 134.46 180 bottom
CM32  0.1U_0402_10V7K  [C_0402]  163.11 131.56 0 bottom
CM33  1U_0603_10V4Z  [C_0603]  149.86 132.27 90 bottom
CM34  0.1U_0402_10V7K  [C_0402]  159.96 137.17 180 bottom
CM35  0.1U_0402_10V7K  [C_0402]  155.96 136.78 90 bottom
CM36  0.1U_0402_10V7K  [C_0402]  155.5 127.9 270 bottom
CM62  0.22U_0402_10V6K  [C_0402]  158.13 125.31 90 bottom
CM63  0.22U_0402_10V6K  [C_0402]  160.06 127.14 90 bottom
CM64  0.22U_0402_10V6K  [C_0402]  157.72 127.14 90 bottom
CM65  0.22U_0402_10V6K  [C_0402]  156.83 127.14 90 bottom
CM66  0.22U_0402_10V6K  [C_0402]  159.2 127.14 90 bottom
CM67  0.22U_0402_10V6K  [C_0402]  162.44 127.14 90 bottom
CM68  0.22U_0402_10V6K  [C_0402]  159.02 125.31 90 bottom
CM69  0.22U_0402_10V6K  [C_0402]  161.55 127.14 90 bottom
CM70  0.1U_0402_10V7K  [C_0402]  156.96 140.54 180 bottom
CM98  0.01U_0603_25V7K  [C_0603]  220.86 125.08 90 bottom
CM99  0.01U_0603_25V7K  [C_0603]  219.65 125.08 90 bottom
CMOS1  SHORT PADS~D  [SHORTPADS]  139.64 46.76 90 bottom
CN1  0.1U_0402_16V4Z~D  [C_0402]  161.77 27.38 90 top
CN2  1000P_0402_50V7K~D  [C_0402]  165.32 23.15 0 top
CN3  0.1U_0402_16V4Z~D  [C_0402]  162.36 25.49 180 top
CN4  1U_0402_6.3V4Z~D  [C_0402]  162.36 24.59 180 top
CN6  47P_0402_50V8J~D  [C_0402]  162.36 23.66 180 top
CN7  0.01U_0402_16V7K  [C_0402]  157.55 21.69 270 top
CN8  0.1U_0402_25V6K  [C_0402]  156.09 11.64 90 top
CN9  0.01U_0402_16V7K  [C_0402]  165.88 15.33 180 top
CN10  0.01U_0402_16V7K  [C_0402]  165.88 16.22 180 top
CN11  0.01U_0402_16V7K  [C_0402]  166.51 18.12 180 top
CN12  0.01U_0402_16V7K  [C_0402]  166.51 17.24 180 top
CN13  0.01U_0402_16V7K  [C_0402]  157.62 15.2 180 top
CN14  0.01U_0402_16V7K  [C_0402]  157.62 16.22 180 top
CN15  0.01U_0402_16V7K  [C_0402]  157.62 18.15 180 top
CN16  0.01U_0402_16V7K  [C_0402]  157.62 17.19 180 top
CN17  0.1U_0402_16V4Z~D  [C_0402]  265.93 6.69 0 top
CN18  10U_0805_10V4Z~D  [C_0805]  265.47 12.98 0 top
CN19  10U_0805_25V6K~D  [C_0805]  229.58 7.85 270 top
CN20  1U_0402_6.3V6K~D  [C_0402]  245.67 6.06 0 top
CN21  0.1U_0402_25V6K~D  [C_0402]  229.62 8.96 0 top
CN22  1000P_0402_50V7K~D  [C_0402]  245.67 6.95 0 top
CN23  10U_0805_25V6K~D  [C_0805]  206.11 7.85 270 top
CN24  1U_0402_6.3V6K~D  [C_0402]  222.18 6.06 0 top
CN25  0.1U_0402_25V6K~D  [C_0402]  206.39 8.99 0 top
CN26  1000P_0402_50V7K~D  [C_0402]  222.18 6.95 0 top
CN27  0.01U_0402_16V7K~D  [C_0402]  236.54 12.35 90 top
CN28  0.01U_0402_16V7K~D  [C_0402]  213.17 13.44 270 top
CN29  0.01U_0402_16V7K~D  [C_0402]  235.65 12.35 90 top
CN30  0.01U_0402_16V7K~D  [C_0402]  212.22 13.44 270 top
CN31  0.01U_0402_16V7K~D  [C_0402]  234.7 12.35 90 top
CN32  0.01U_0402_16V7K~D  [C_0402]  211.14 13.44 270 top
CN33  0.01U_0402_16V7K~D  [C_0402]  233.68 12.35 90 top
CN34  0.01U_0402_16V7K~D  [C_0402]  210.19 13.44 270 top
CN35  0.1U_0402_25V6K~D  [C_0402]  196.08 6.95 0 top
CN36  1000P_0402_50V7K~D  [C_0402]  179.72 8.96 0 top
CN37  10U_0805_25V6K~D  [C_0805]  179.97 7.83 270 top
CN38  1U_0402_6.3V6K~D  [C_0402]  196.08 6.06 0 top
CN39  10U_0805_25V6K~D  [C_0805]  156.96 7.84 270 top
CN40  1U_0402_6.3V6K~D  [C_0402]  172.52 6.06 0 top
CN41  0.1U_0402_25V6K~D  [C_0402]  172.52 6.95 0 top
CN42  1000P_0402_50V7K~D  [C_0402]  157.43 8.94 0 top
CN43  0.01U_0402_16V7K~D  [C_0402]  163.69 9.37 90 top
CN44  0.01U_0402_16V7K~D  [C_0402]  187.1 16.83 270 top
CN45  0.01U_0402_16V7K~D  [C_0402]  162.75 9.37 90 top
CN46  0.01U_0402_16V7K~D  [C_0402]  186.17 16.83 270 top
CN47  0.01U_0402_16V7K~D  [C_0402]  161.8 9.37 90 top
CN48  0.01U_0402_16V7K~D  [C_0402]  185.17 16.83 270 top
CN49  0.01U_0402_16V7K~D  [C_0402]  160.85 9.37 90 top
CN50  0.01U_0402_16V7K~D  [C_0402]  184.28 16.83 270 top
CN51  4.7U_0603_10V  [C_0603]  165.05 24.22 0 top
CN52  4.7U_0603_10V  [C_0603]  165.05 25.49 0 top
CPU1  HASWELL_BGA1364  [HASWELL_BGA_1364P-T]  128.22 102.07 0 bottom
CR1  10U_0603_6.3V6M  [C_0603]  332.58 18.02 270 top
CR2  0.1U_0402_16V7K  [C_0402]  331.42 18.02 270 top
CR3  1U_0402_6.3V6K  [C_0402]  328.3 24.12 270 top
CR4  0.1U_0402_16V7K  [C_0402]  331.08 15.52 0 top
CR5  4.7U_0603_6.3V6K  [C_0603]  332.59 20.51 270 top
CR6  4.7U_0603_6.3V6K  [C_0603]  322.2 19.83 90 top
CR7  0.1U_0402_16V7K  [C_0402]  323.31 19.79 90 top
CR8  0.1U_0402_16V7K  [C_0402]  331.46 20.51 270 top
CR9  5P_0402_50V8C  [C_0402]  299.3 19.45 270 bottom
CR10  0.1U_0402_16V7K  [C_0402]  328.36 13.95 90 top
CR11  0.1U_0402_16V7K  [C_0402]  329.27 13.95 90 top
CR12  10U_0603_6.3V6M  [C_0603]  302.9 24.28 180 top
CR13  0.1U_0402_16V7K  [C_0402]  302.59 31.14 180 top
CR14  5P_0402_50V8C  [C_0402]  299.3 35.4 90 bottom
CT2  2200P_0402_25V7K  [C_0402]  193.17 132.93 180 bottom
CT3  0.1U_0402_10V6K  [C_0402]  193.17 131.96 180 bottom
CT4  1U_0402_6.3V6K  [C_0402]  199.19 133.15 90 bottom
CT5  0.1U_0402_25V6  [C_0402]  250.05 39.4 0 bottom
CT6  4700P_0402_25V7K  [C_0402]  250.05 34.83 0 bottom
CT7  2200P_0402_50V7K  [C_0402]  240.68 38.36 180 bottom
CT8  0.1U_0402_25V6  [C_0402]  238.89 35.09 270 bottom
CU26  0.1U_0402_16V7K  [C_0402]  16.62 40.6 180 top
CU27  2.2U_0603_6.3V6K  [C_0603]  15.4 36.98 180 top
CU28  0.1U_0402_16V7K  [C_0402]  13.93 35.78 0 top
CU29  0.1U_0402_16V7K  [C_0402]  16.68 35.78 180 top
CV1  0.1U_0402_16V7K  [C_0402]  103.51 136.55 135 bottom
CV2  0.1U_0402_16V7K  [C_0402]  102.88 135.92 135 bottom
CV3  0.1U_0402_16V7K  [C_0402]  102.21 135.27 135 bottom
CV4  0.1U_0402_16V7K  [C_0402]  101.54 134.6 135 bottom
CV5  4.7U_0805_10V4Z  [C_0805]  81.26 118.57 315 bottom
CV6  0.1U_0402_16V7K  [C_0402]  100.27 133.35 135 bottom
CV7  0.1U_0402_16V7K  [C_0402]  99.62 132.69 135 bottom
CV8  0.1U_0402_16V7K  [C_0402]  100.9 133.98 135 bottom
CV9  0.1U_0402_10V7K  [C_0402]  87.19 121.19 225 bottom
CV10  4.7U_0805_10V4Z  [C_0805]  86.17 123.97 45 bottom
CV11  0.1U_0402_16V7K  [C_0402]  98.98 132.04 135 bottom
CV12  0.1U_0402_16V7K  [C_0402]  98.31 131.38 135 bottom
CV13  0.1U_0402_16V7K  [C_0402]  97.68 130.75 135 bottom
CV14  0.1U_0603_25V7K  [C_0603]  82.23 118.77 180 top
CV15  1000P_0402_50V7K  [C_0402]  85.92 114.51 135 top
CV16  0.1U_0402_10V7K  [C_0402]  91.8 124.05 225 bottom
CV17  0.1U_0402_10V7K  [C_0402]  96.59 124.3 315 top
CV18  10U_0805_10V6K  [C_0805]  87.44 122.7 45 bottom
CV19  0.1U_0402_10V7K  [C_0402]  100.22 128.25 315 top
CV21  4.7U_0805_10V4Z  [C_0805]  88.45 126.13 315 bottom
CV23  0.1U_0402_10V6K  [C_0402]  154.76 147.54 180 bottom
CV24  0.1U_0402_10V7K  [C_0402]  153.94 138.34 270 bottom
CV25  0.1U_0402_10V7K  [C_0402]  152.97 138.34 270 bottom
CV26  0.1U_0402_10V7K~D  [C_0402]  140.27 138 90 top
CV27  0.1U_0402_10V7K~D  [C_0402]  141.16 138 90 top
CV28  0.1U_0402_10V7K~D  [C_0402]  142.05 138 90 top
CV29  0.1U_0402_10V7K~D  [C_0402]  141.89 136.01 90 bottom
CV30  0.1U_0402_10V7K~D  [C_0402]  142.94 138 90 top
CV31  0.1U_0402_10V7K~D  [C_0402]  142.84 136.01 90 bottom
CV32  0.1U_0402_10V7K~D  [C_0402]  143.89 138 90 top
CV33  0.1U_0402_10V7K~D  [C_0402]  144.78 138 90 top
